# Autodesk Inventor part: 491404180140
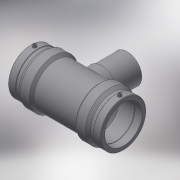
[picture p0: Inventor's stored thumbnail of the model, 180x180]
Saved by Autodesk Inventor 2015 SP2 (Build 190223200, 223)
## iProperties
Created: 2017-06
Part Number: 491404180140
Material: Generic
Description: PLASSON REDUCING TEE 180x140x180
Document SubType Name: Modeling
Designer: KIM
Mass: 7993.01 g
Surface Area: 6776.22 cm^2
Volume: 7993.01 cm^3
Density: 1 g/cm^3
Appearance: Default
Author: KIM
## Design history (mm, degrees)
derived "491404.ipt"
feature "Solid1::491404.ipt"
tag "TaggingFeature1"
body "Solid1"
other parameters: "d0" = 422, "d2" = 245, "d3" = 106, "d4" = 84.4, "d5" = 220.5, "d6" = 171, "d8" = 168 deg, "d10" = 42.4, "d11" = 14.13333, "d13" = 422, "d14" = 17.6296, "d17" = 162, "d19" = 3.52592, "d20" = 168 deg, "d22" = 227.85, "d23" = 245, "d25" = 135 deg, "d26" = 295.4, "d29" = 116, "d30" = 15, "d31" = 168.8, "d34" = 5 deg, "d35" = 15, "d39" = 5 deg, "d41" = 4, "d42" = 14, "d43" = 0, "d45" = 4, "d46" = 6, "d47" = 0, "d48" = -237, "d51" = 0, "d52" = 112, "d54" = 0, "d55" = 220.5, "d56" = 245, "d57" = 147.7, "d58" = 135 deg, "d59" = 106, "d60" = 106, "d61" = 135 deg, "d62" = 237, "d72" = 192.01, "d73" = 96.005, "d74" = -237, "d75" = 147, "d77" = 0, "d78" = 112, "d80" = 0, "d82" = 114.5, "d83" = 0, "d84" = 3, "d85" = 0, "d86" = 35.33333, "d87" = 223.293, "d88" = 14.13333, "d89" = 3, "d90" = 0, "L_" = 422, "L_1" = 106, "D_" = 245, "A_" = 116, "d_2" = 12, "H_" = 237
